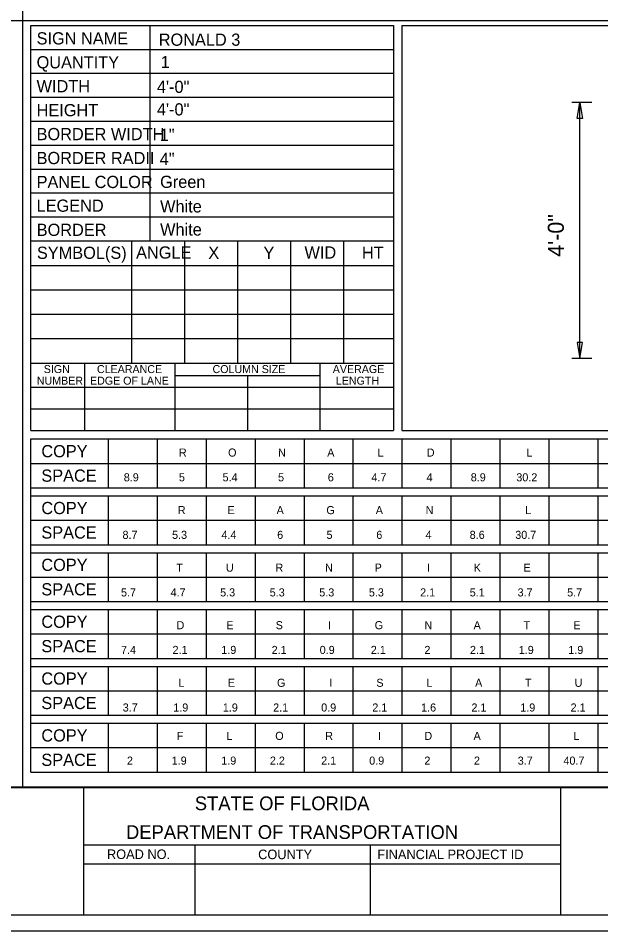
# Model space of a CAD drawing. Extents: x 17890628 to 17890844, y 17897693 to 17898031.
# Drawn here: x 17890772.14 to 17890803.98, y 17897907.61 to 17897957.5 of the extents above; entities that cross this region are included whole.
import ezdxf

# ---------------------------------------------------------------- set-up
doc = ezdxf.new("R2010")
doc.units = 0
for name, color, linetype in [('GSDims', 7, 'Continuous'), ('GSSign', 7, 'Continuous'), ('PlotBorder_dp', 7, 'Continuous'), ('SheetBorder_dp', 7, 'Continuous'), ('SheetLines_dp', 7, 'Continuous'), ('SheetLinesMisc2_dp', 7, 'Continuous'), ('TextMinor', 7, 'Continuous'), ('TextMisc', 7, 'Continuous')]:
    doc.layers.add(name, color=color, linetype=linetype)

msp = doc.modelspace()

# ---------------------------------------------------------------- linework, layer by layer
at = {"layer": 'GSDims'}
for p, q in [((17890803.49, 17897952.897), (17890802.396, 17897952.897)), ((17890802.834, 17897938.897), (17890802.834, 17897952.897)), ((17890803.49, 17897938.897), (17890802.396, 17897938.897))]:
    msp.add_line(p, q, dxfattribs=at)
for points in [[(17890802.834, 17897952.897), (17890802.98, 17897952.022), (17890802.688, 17897952.022)], [(17890802.834, 17897938.897), (17890802.98, 17897939.772), (17890802.688, 17897939.772)]]:
    msp.add_lwpolyline(points, close=True, dxfattribs=at)
at = {"layer": 'PlotBorder_dp'}
msp.add_lwpolyline([(17890700.471, 17897907.61), (17890843.989, 17897907.61), (17890843.989, 17897999.809), (17890700.471, 17897999.809)], close=True, dxfattribs=at)
at = {"layer": 'SheetBorder_dp'}
for p, q in [((17890705.254, 17897915.438), (17890839.205, 17897915.438)), ((17890705.254, 17897908.479), (17890839.205, 17897908.479))]:
    msp.add_line(p, q, dxfattribs=at)
at = {"layer": 'SheetLines_dp'}
for p, q in [((17890775.709, 17897915.438), (17890775.709, 17897908.479)), ((17890801.803, 17897908.479), (17890801.803, 17897915.438)), ((17890775.709, 17897912.307), (17890801.803, 17897912.307)), ((17890781.798, 17897912.307), (17890781.798, 17897908.479)), ((17890791.366, 17897912.307), (17890791.366, 17897908.479)), ((17890775.709, 17897911.263), (17890801.803, 17897911.263))]:
    msp.add_line(p, q, dxfattribs=at)
at = {"layer": 'SheetLinesMisc2_dp'}
for p, q in [((17890772.367, 17897998.732), (17890772.367, 17897915.484)), ((17890705.5, 17897957.37), (17890839.233, 17897957.37)), ((17890772.823, 17897934.954), (17890772.823, 17897957.109)), ((17890772.823, 17897957.109), (17890792.654, 17897957.109)), ((17890779.324, 17897957.109), (17890779.324, 17897945.329)), ((17890792.654, 17897957.109), (17890792.654, 17897934.954)), ((17890793.11, 17897957.109), (17890793.11, 17897934.985)), ((17890793.11, 17897957.108), (17890838.594, 17897957.108)), ((17890772.823, 17897955.801), (17890792.654, 17897955.801)), ((17890772.823, 17897954.492), (17890792.654, 17897954.492)), ((17890772.823, 17897953.183), (17890792.654, 17897953.183)), ((17890772.823, 17897951.875), (17890792.654, 17897951.875)), ((17890772.823, 17897950.566), (17890792.654, 17897950.566)), ((17890772.823, 17897949.257), (17890792.654, 17897949.257)), ((17890772.823, 17897947.949), (17890782.738, 17897947.949)), ((17890782.738, 17897947.949), (17890792.654, 17897947.949)), ((17890772.823, 17897946.64), (17890782.738, 17897946.64)), ((17890782.738, 17897946.64), (17890792.654, 17897946.64)), ((17890772.823, 17897945.329), (17890792.654, 17897945.329)), ((17890778.326, 17897945.329), (17890778.326, 17897938.647)), ((17890781.223, 17897945.329), (17890781.223, 17897938.647)), ((17890784.121, 17897945.329), (17890784.121, 17897938.647)), ((17890787.018, 17897945.329), (17890787.018, 17897938.647)), ((17890789.916, 17897945.329), (17890789.916, 17897938.647)), ((17890772.823, 17897943.992), (17890792.654, 17897943.992)), ((17890772.823, 17897942.656), (17890792.654, 17897942.656)), ((17890772.823, 17897941.32), (17890792.654, 17897941.32)), ((17890772.823, 17897939.984), (17890792.654, 17897939.984)), ((17890772.823, 17897938.647), (17890792.654, 17897938.647)), ((17890775.761, 17897938.647), (17890775.761, 17897934.955)), ((17890780.696, 17897938.647), (17890780.696, 17897934.955)), ((17890788.628, 17897938.647), (17890788.628, 17897934.955)), ((17890780.696, 17897937.967), (17890788.628, 17897937.967)), ((17890784.663, 17897937.967), (17890784.663, 17897934.955)), ((17890772.823, 17897937.328), (17890792.654, 17897937.328)), ((17890772.823, 17897936.141), (17890792.654, 17897936.141)), ((17890772.823, 17897934.954), (17890792.654, 17897934.954)), ((17890793.11, 17897934.953), (17890838.594, 17897934.953)), ((17890772.824, 17897934.497), (17890838.594, 17897934.497)), ((17890772.824, 17897916.286), (17890772.824, 17897934.497)), ((17890777.058, 17897934.497), (17890777.058, 17897931.825)), ((17890779.733, 17897934.497), (17890779.733, 17897931.825)), ((17890782.408, 17897934.497), (17890782.408, 17897931.825)), ((17890785.084, 17897934.497), (17890785.084, 17897931.825)), ((17890787.76, 17897934.497), (17890787.76, 17897931.825)), ((17890790.435, 17897934.497), (17890790.435, 17897931.825)), ((17890793.11, 17897934.497), (17890793.11, 17897931.825)), ((17890795.786, 17897934.497), (17890795.786, 17897931.825)), ((17890798.462, 17897934.497), (17890798.462, 17897931.825)), ((17890801.137, 17897934.497), (17890801.137, 17897931.825)), ((17890803.813, 17897934.497), (17890803.813, 17897931.825)), ((17890772.824, 17897933.162), (17890838.594, 17897933.162)), ((17890772.824, 17897931.825), (17890838.594, 17897931.825)), ((17890772.824, 17897931.389), (17890838.594, 17897931.389)), ((17890777.058, 17897931.389), (17890777.058, 17897928.717)), ((17890779.733, 17897931.389), (17890779.733, 17897928.717)), ((17890782.408, 17897931.389), (17890782.408, 17897928.717)), ((17890785.084, 17897931.389), (17890785.084, 17897928.717)), ((17890787.76, 17897931.389), (17890787.76, 17897928.717)), ((17890790.435, 17897931.389), (17890790.435, 17897928.717)), ((17890793.11, 17897931.389), (17890793.11, 17897928.717)), ((17890795.786, 17897931.389), (17890795.786, 17897928.717)), ((17890798.462, 17897931.389), (17890798.462, 17897928.717)), ((17890801.137, 17897931.389), (17890801.137, 17897928.717)), ((17890803.813, 17897931.389), (17890803.813, 17897928.717)), ((17890772.824, 17897930.053), (17890838.594, 17897930.053)), ((17890772.824, 17897928.717), (17890838.594, 17897928.717)), ((17890772.824, 17897928.281), (17890838.594, 17897928.281)), ((17890777.058, 17897928.281), (17890777.058, 17897925.609)), ((17890779.733, 17897928.281), (17890779.733, 17897925.609)), ((17890782.408, 17897928.281), (17890782.408, 17897925.609)), ((17890785.084, 17897928.281), (17890785.084, 17897925.609)), ((17890787.76, 17897928.281), (17890787.76, 17897925.609)), ((17890790.435, 17897928.281), (17890790.435, 17897925.609)), ((17890793.11, 17897928.281), (17890793.11, 17897925.609)), ((17890795.786, 17897928.281), (17890795.786, 17897925.609)), ((17890798.462, 17897928.281), (17890798.462, 17897925.609)), ((17890801.137, 17897928.281), (17890801.137, 17897925.609)), ((17890803.813, 17897928.281), (17890803.813, 17897925.609)), ((17890772.824, 17897926.945), (17890838.594, 17897926.945)), ((17890772.824, 17897925.609), (17890838.594, 17897925.609)), ((17890772.824, 17897925.173), (17890838.594, 17897925.173)), ((17890777.058, 17897925.173), (17890777.058, 17897922.501)), ((17890779.733, 17897925.173), (17890779.733, 17897922.501)), ((17890782.408, 17897925.173), (17890782.408, 17897922.501)), ((17890785.084, 17897925.173), (17890785.084, 17897922.501)), ((17890787.76, 17897925.173), (17890787.76, 17897922.501)), ((17890790.435, 17897925.173), (17890790.435, 17897922.501)), ((17890793.11, 17897925.173), (17890793.11, 17897922.501)), ((17890795.786, 17897925.173), (17890795.786, 17897922.501)), ((17890798.462, 17897925.173), (17890798.462, 17897922.501)), ((17890801.137, 17897925.173), (17890801.137, 17897922.501)), ((17890803.813, 17897925.173), (17890803.813, 17897922.501)), ((17890772.824, 17897923.838), (17890838.594, 17897923.838)), ((17890772.824, 17897922.501), (17890838.594, 17897922.501)), ((17890772.824, 17897922.065), (17890838.594, 17897922.065)), ((17890777.058, 17897922.065), (17890777.058, 17897919.393)), ((17890779.733, 17897922.065), (17890779.733, 17897919.393)), ((17890782.408, 17897922.065), (17890782.408, 17897919.393)), ((17890785.084, 17897922.065), (17890785.084, 17897919.393)), ((17890787.76, 17897922.065), (17890787.76, 17897919.393)), ((17890790.435, 17897922.065), (17890790.435, 17897919.393)), ((17890793.11, 17897922.065), (17890793.11, 17897919.393)), ((17890795.786, 17897922.065), (17890795.786, 17897919.393)), ((17890798.462, 17897922.065), (17890798.462, 17897919.393)), ((17890801.137, 17897922.065), (17890801.137, 17897919.393)), ((17890803.813, 17897922.065), (17890803.813, 17897919.393)), ((17890772.824, 17897920.729), (17890838.594, 17897920.729)), ((17890772.824, 17897919.393), (17890838.594, 17897919.393)), ((17890772.824, 17897918.958), (17890838.594, 17897918.958)), ((17890777.058, 17897918.958), (17890777.058, 17897916.286)), ((17890779.733, 17897918.958), (17890779.733, 17897916.286)), ((17890782.408, 17897918.958), (17890782.408, 17897916.286)), ((17890785.084, 17897918.958), (17890785.084, 17897916.286)), ((17890787.76, 17897918.958), (17890787.76, 17897916.286)), ((17890790.435, 17897918.958), (17890790.435, 17897916.286)), ((17890793.11, 17897918.958), (17890793.11, 17897916.286)), ((17890795.786, 17897918.958), (17890795.786, 17897916.286)), ((17890798.462, 17897918.958), (17890798.462, 17897916.286)), ((17890801.137, 17897918.958), (17890801.137, 17897916.286)), ((17890803.813, 17897918.958), (17890803.813, 17897916.286)), ((17890772.824, 17897917.622), (17890838.594, 17897917.622)), ((17890772.824, 17897916.286), (17890838.594, 17897916.286)), ((17890705.5, 17897915.484), (17890839.233, 17897915.484))]:
    msp.add_line(p, q, dxfattribs=at)

# ---------------------------------------------------------------- texts
at = {"layer": 'GSDims'}
msp.add_text('4\'-0"', height=0.875, rotation=90, dxfattribs=at).set_placement((17890801.959, 17897944.461))
at = {"layer": 'GSSign'}
for s, height, p in [('RONALD 3', 0.6667, (17890779.817, 17897955.998)), ('1', 0.667, (17890779.925, 17897954.774)), ('4\'-0"', 0.6667, (17890779.716, 17897953.42)), ('4\'-0"', 0.6667, (17890779.716, 17897952.186)), ('1"', 0.6667, (17890779.871, 17897950.79)), ('4"', 0.6667, (17890779.871, 17897949.479)), ('Green', 0.6667, (17890779.892, 17897948.225)), ('White', 0.6667, (17890779.892, 17897946.883)), ('White', 0.6667, (17890779.892, 17897945.619)), ('R', 0.441, (17890780.92, 17897933.535)), ('O', 0.441, (17890783.608, 17897933.535)), ('N', 0.441, (17890786.339, 17897933.535)), ('A', 0.441, (17890789.027, 17897933.535)), ('L', 0.441, (17890791.778, 17897933.535)), ('D', 0.441, (17890794.467, 17897933.535)), ('L', 0.441, (17890799.906, 17897933.535)), ('8.9', 0.4411, (17890777.906, 17897932.182)), ('5', 0.441, (17890780.92, 17897932.182)), ('5.4', 0.4411, (17890783.304, 17897932.182)), ('5', 0.441, (17890786.339, 17897932.182)), ('6', 0.441, (17890789.058, 17897932.182)), ('4.7', 0.4411, (17890791.442, 17897932.182)), ('4', 0.441, (17890794.456, 17897932.182)), ('8.9', 0.4411, (17890796.871, 17897932.182)), ('30.2', 0.4411, (17890799.36, 17897932.182)), ('R', 0.441, (17890780.861, 17897930.388)), ('E', 0.441, (17890783.581, 17897930.388)), ('A', 0.441, (17890786.259, 17897930.388)), ('G', 0.441, (17890788.979, 17897930.388)), ('A', 0.441, (17890791.678, 17897930.388)), ('N', 0.441, (17890794.408, 17897930.388)), ('L', 0.441, (17890799.848, 17897930.388)), ('8.7', 0.4411, (17890777.837, 17897929.036)), ('5.3', 0.4411, (17890780.546, 17897929.036)), ('4.4', 0.4411, (17890783.245, 17897929.036)), ('6', 0.441, (17890786.291, 17897929.036)), ('5', 0.441, (17890788.989, 17897929.036)), ('6', 0.441, (17890791.709, 17897929.036)), ('4', 0.441, (17890794.398, 17897929.036)), ('8.6', 0.4411, (17890796.813, 17897929.036)), ('30.7', 0.4411, (17890799.302, 17897929.036)), ('T', 0.441, (17890780.78, 17897927.242)), ('U', 0.441, (17890783.489, 17897927.242)), ('R', 0.441, (17890786.198, 17897927.242)), ('N', 0.441, (17890788.908, 17897927.242)), ('P', 0.441, (17890791.617, 17897927.242)), ('I', 0.441, (17890794.473, 17897927.242)), ('K', 0.441, (17890797.035, 17897927.242)), ('E', 0.441, (17890799.755, 17897927.242)), ('5.7', 0.4411, (17890777.755, 17897925.889)), ('4.7', 0.4411, (17890780.464, 17897925.889)), ('5.3', 0.4411, (17890783.174, 17897925.889)), ('5.3', 0.4411, (17890785.883, 17897925.889)), ('5.3', 0.4411, (17890788.592, 17897925.889)), ('5.3', 0.4411, (17890791.302, 17897925.889)), ('2.1', 0.4411, (17890794.106, 17897925.889)), ('5.1', 0.4411, (17890796.815, 17897925.889)), ('3.7', 0.4411, (17890799.43, 17897925.889)), ('5.7', 0.4411, (17890802.139, 17897925.889)), ('D', 0.441, (17890780.791, 17897924.095)), ('E', 0.441, (17890783.511, 17897924.095)), ('S', 0.441, (17890786.21, 17897924.095)), ('I', 0.441, (17890789.066, 17897924.095)), ('G', 0.441, (17890791.618, 17897924.095)), ('N', 0.441, (17890794.338, 17897924.095)), ('A', 0.441, (17890797.026, 17897924.095)), ('T', 0.441, (17890799.757, 17897924.095)), ('E', 0.441, (17890802.476, 17897924.095)), ('7.4', 0.4411, (17890777.756, 17897922.743)), ('2.1', 0.4411, (17890780.571, 17897922.743)), ('1.9', 0.4411, (17890783.238, 17897922.743)), ('2.1', 0.4411, (17890785.989, 17897922.743)), ('0.9', 0.4411, (17890788.615, 17897922.743)), ('2.1', 0.4411, (17890791.408, 17897922.743)), ('2', 0.441, (17890794.338, 17897922.743)), ('2.1', 0.4411, (17890796.827, 17897922.743)), ('1.9', 0.4411, (17890799.494, 17897922.743)), ('1.9', 0.4411, (17890802.203, 17897922.743)), ('L', 0.441, (17890780.894, 17897920.948)), ('E', 0.441, (17890783.593, 17897920.948)), ('G', 0.441, (17890786.281, 17897920.948)), ('I', 0.441, (17890789.148, 17897920.948)), ('S', 0.441, (17890791.71, 17897920.948)), ('L', 0.441, (17890794.441, 17897920.948)), ('A', 0.441, (17890797.108, 17897920.948)), ('T', 0.441, (17890799.838, 17897920.948)), ('U', 0.441, (17890802.548, 17897920.948)), ('3.7', 0.4411, (17890777.849, 17897919.596)), ('1.9', 0.4411, (17890780.611, 17897919.596)), ('1.9', 0.4411, (17890783.32, 17897919.596)), ('2.1', 0.4411, (17890786.071, 17897919.596)), ('0.9', 0.4411, (17890788.696, 17897919.596)), ('2.1', 0.4411, (17890791.49, 17897919.596)), ('1.6', 0.4411, (17890794.157, 17897919.596)), ('2.1', 0.4411, (17890796.908, 17897919.596)), ('1.9', 0.4411, (17890799.576, 17897919.596)), ('2.1', 0.4411, (17890802.327, 17897919.596)), ('F', 0.441, (17890780.799, 17897918.044)), ('L', 0.441, (17890783.518, 17897918.044)), ('O', 0.441, (17890786.186, 17897918.044)), ('R', 0.441, (17890788.916, 17897918.044)), ('I', 0.441, (17890791.802, 17897918.044)), ('D', 0.441, (17890794.335, 17897918.044)), ('A', 0.441, (17890797.023, 17897918.044)), ('L', 0.441, (17890802.484, 17897918.044)), ('2', 0.441, (17890778.079, 17897916.692)), ('1.9', 0.4411, (17890780.525, 17897916.692)), ('1.9', 0.4411, (17890783.235, 17897916.692)), ('2.2', 0.4411, (17890785.892, 17897916.692)), ('2.1', 0.4411, (17890788.695, 17897916.692)), ('0.9', 0.4411, (17890791.321, 17897916.692)), ('2', 0.441, (17890794.335, 17897916.692)), ('2', 0.441, (17890797.044, 17897916.692)), ('3.7', 0.4411, (17890799.438, 17897916.692)), ('40.7', 0.4411, (17890801.937, 17897916.692))]:
    msp.add_text(s, height=height, dxfattribs=at).set_placement(p)
at = {"layer": 'TextMinor'}
for s, height, p in [('SIGN NAME', 0.6667, (17890773.142, 17897956.069)), ('QUANTITY', 0.6667, (17890773.142, 17897954.761)), ('WIDTH', 0.6667, (17890773.142, 17897953.452)), ('HEIGHT', 0.6667, (17890773.142, 17897952.144)), ('BORDER WIDTH', 0.66667, (17890773.142, 17897950.835)), ('BORDER RADII', 0.66667, (17890773.142, 17897949.526)), ('PANEL COLOR', 0.66667, (17890773.142, 17897948.218)), ('LEGEND', 0.6667, (17890773.142, 17897946.921)), ('BORDER', 0.6667, (17890773.148, 17897945.6)), ('SYMBOL(S)', 0.6667, (17890773.16, 17897944.346)), ('ANGLE', 0.6667, (17890778.58, 17897944.36)), ('X', 0.667, (17890782.527, 17897944.346)), ('Y', 0.667, (17890785.54, 17897944.346)), ('WID', 0.6667, (17890787.784, 17897944.36)), ('HT', 0.6667, (17890790.925, 17897944.348)), ('SIGN', 0.4357, (17890773.533, 17897938.103)), ('CLEARANCE', 0.4357, (17890776.44, 17897938.101)), ('COLUMN SIZE', 0.43573, (17890782.758, 17897938.101)), ('AVERAGE', 0.4357, (17890789.329, 17897938.101)), ('NUMBER', 0.4357, (17890773.154, 17897937.469)), ('EDGE OF LANE', 0.43573, (17890776.061, 17897937.469)), ('LENGTH', 0.4357, (17890789.498, 17897937.469)), ('COPY', 0.6667, (17890773.402, 17897933.498)), ('SPACE', 0.6667, (17890773.402, 17897932.162)), ('COPY', 0.6667, (17890773.402, 17897930.389)), ('SPACE', 0.6667, (17890773.402, 17897929.053)), ('COPY', 0.6667, (17890773.402, 17897927.282)), ('SPACE', 0.6667, (17890773.402, 17897925.946)), ('COPY', 0.6667, (17890773.402, 17897924.173)), ('SPACE', 0.6667, (17890773.402, 17897922.838)), ('COPY', 0.6667, (17890773.402, 17897921.065)), ('SPACE', 0.6667, (17890773.402, 17897919.729)), ('COPY', 0.6667, (17890773.402, 17897917.958)), ('SPACE', 0.6667, (17890773.402, 17897916.622))]:
    msp.add_text(s, height=height, dxfattribs=at).set_placement(p)
at = {"layer": 'TextMisc'}
for s, height, p in [('STATE OF FLORIDA', 0.75151, (17890781.788, 17897914.2)), ('DEPARTMENT OF TRANSPORTATION', 0.75151, (17890778.029, 17897912.63)), ('ROAD NO.', 0.5219, (17890776.988, 17897911.533)), ('COUNTY', 0.5219, (17890785.251, 17897911.524)), ('FINANCIAL PROJECT ID', 0.52189, (17890791.765, 17897911.524))]:
    msp.add_text(s, height=height, dxfattribs=at).set_placement(p)

doc.saveas('drawing.dxf')
